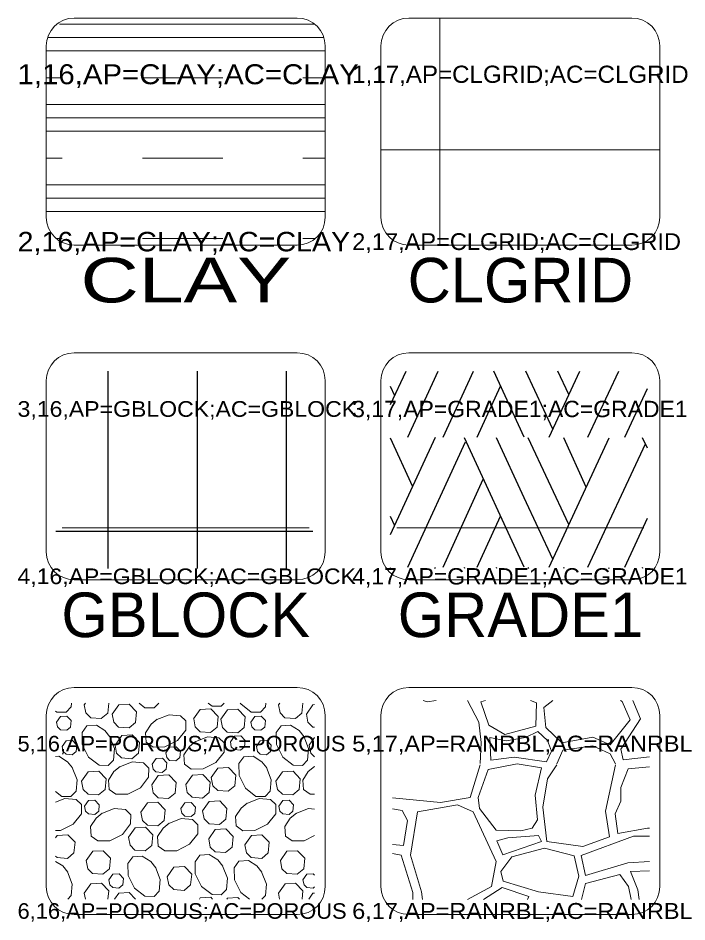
# Model space of a CAD drawing. Extents: x 95935 to 95946.4, y 95971.2 to 95974.7.
# Drawn here: x 95944.035 to 95945.234, y 95973.111 to 95974.732 of the extents above; entities that cross this region are included whole.
import ezdxf
from ezdxf.enums import TextEntityAlignment as Align

# ---------------------------------------------------------------- set-up
doc = ezdxf.new("R2010")
doc.units = 0
doc.header["$LTSCALE"] = 0.013
for name, color, linetype, lineweight in [('1', 7, 'Continuous', 13), ('25', 7, 'Continuous', 13), ('6', 7, 'Continuous', 13), ('63', 7, 'Continuous', 13)]:
    doc.layers.add(name, color=color, linetype=linetype, lineweight=lineweight)
doc.layers.add('20', color=7, linetype='Continuous')

msp = doc.modelspace()

# ---------------------------------------------------------------- linework, layer by layer
at = {"layer": '1'}
for p, q in [((95944.1357, 95974.7318), (95944.5357, 95974.7318)), ((95944.7357, 95974.7318), (95945.1357, 95974.7318)), ((95944.0857, 95974.3747), (95944.0857, 95974.6818)), ((95944.5857, 95974.6818), (95944.5857, 95974.3747)), ((95944.6857, 95974.3747), (95944.6857, 95974.6818)), ((95945.1857, 95974.6818), (95945.1857, 95974.3747)), ((95944.5357, 95974.3247), (95944.1357, 95974.3247)), ((95945.1357, 95974.3247), (95944.7357, 95974.3247)), ((95944.1357, 95974.1318), (95944.5357, 95974.1318)), ((95944.7357, 95974.1318), (95945.1357, 95974.1318)), ((95944.0857, 95973.7747), (95944.0857, 95974.0818)), ((95944.5857, 95974.0818), (95944.5857, 95973.7747)), ((95944.6857, 95973.7747), (95944.6857, 95974.0818)), ((95945.1857, 95974.0818), (95945.1857, 95973.7747)), ((95944.5357, 95973.7247), (95944.1357, 95973.7247)), ((95945.1357, 95973.7247), (95944.7357, 95973.7247)), ((95944.1357, 95973.5318), (95944.5357, 95973.5318)), ((95944.7357, 95973.5318), (95945.1357, 95973.5318)), ((95944.0857, 95973.1747), (95944.0857, 95973.4818)), ((95944.5857, 95973.4818), (95944.5857, 95973.1747)), ((95944.6857, 95973.1747), (95944.6857, 95973.4818)), ((95945.1857, 95973.4818), (95945.1857, 95973.1747)), ((95944.5357, 95973.1247), (95944.1357, 95973.1247)), ((95945.1357, 95973.1247), (95944.7357, 95973.1247))]:
    msp.add_line(p, q, dxfattribs=at)
for centre, start, end in [((95944.1357, 95974.6818), 90, 180), ((95944.5357, 95974.6818), 0, 90), ((95944.7357, 95974.6818), 90, 180), ((95945.1357, 95974.6818), 0, 90), ((95944.1357, 95974.3747), 180, 270), ((95944.5357, 95974.3747), 270, 0), ((95944.7357, 95974.3747), 180, 270), ((95945.1357, 95974.3747), 270, 0), ((95944.1357, 95974.0818), 90, 180), ((95944.5357, 95974.0818), 0, 90), ((95944.7357, 95974.0818), 90, 180), ((95945.1357, 95974.0818), 0, 90), ((95944.1357, 95973.7747), 180, 270), ((95944.5357, 95973.7747), 270, 0), ((95944.7357, 95973.7747), 180, 270), ((95945.1357, 95973.7747), 270, 0), ((95944.1357, 95973.4818), 90, 180), ((95944.5357, 95973.4818), 0, 90), ((95944.7357, 95973.4818), 90, 180), ((95945.1357, 95973.4818), 0, 90), ((95944.1357, 95973.1747), 180, 270), ((95944.5357, 95973.1747), 270, 0), ((95944.7357, 95973.1747), 180, 270), ((95945.1357, 95973.1747), 270, 0)]:
    msp.add_arc(centre, 0.05, start, end, dxfattribs=at)
at = {"layer": '25'}
for p, q in [((95944.5569, 95973.8178), (95944.1141, 95973.8178)), ((95945.1569, 95973.8178), (95944.7141, 95973.8178))]:
    msp.add_line(p, q, dxfattribs=at)
at = {"layer": '6'}
for p, q in [((95944.7912, 95974.7318), (95944.7912, 95974.3247)), ((95944.1094, 95974.7208), (95944.5657, 95974.7208)), ((95944.0887, 95974.6968), (95944.5827, 95974.6968)), ((95944.0857, 95974.6728), (95944.5857, 95974.6728)), ((95944.0857, 95974.6248), (95944.1139, 95974.6248)), ((95944.2579, 95974.6248), (95944.4019, 95974.6248)), ((95944.5459, 95974.6248), (95944.5857, 95974.6248)), ((95944.0857, 95974.5768), (95944.5857, 95974.5768)), ((95944.0857, 95974.5528), (95944.5857, 95974.5528)), ((95944.0857, 95974.5288), (95944.5857, 95974.5288)), ((95944.6857, 95974.4957), (95945.1857, 95974.4957)), ((95944.0857, 95974.4808), (95944.1139, 95974.4808)), ((95944.2579, 95974.4808), (95944.4019, 95974.4808)), ((95944.5459, 95974.4808), (95944.5857, 95974.4808)), ((95944.0857, 95974.4328), (95944.5857, 95974.4328)), ((95944.0857, 95974.4088), (95944.5857, 95974.4088)), ((95944.0857, 95974.3848), (95944.5857, 95974.3848)), ((95944.1041, 95974.3368), (95944.1139, 95974.3368)), ((95944.2579, 95974.3368), (95944.4019, 95974.3368)), ((95944.5459, 95974.3368), (95944.5673, 95974.3368)), ((95944.1537, 95973.5007), (95944.1559, 95973.5038)), ((95944.502, 95973.5007), (95944.5042, 95973.5038)), ((95944.8729, 95973.5082), (95944.8646, 95973.5063)), ((95944.5572, 95973.4286), (95944.5667, 95973.4421)), ((95945.1672, 95973.4073), (95945.12, 95973.4022)), ((95944.5655, 95973.3895), (95944.5667, 95973.39)), ((95944.7066, 95973.2505), (95944.7259, 95973.2487)), ((95945.0527, 95973.1801), (95945.0454, 95973.1517)), ((95944.1558, 95973.1523), (95944.1537, 95973.1628)), ((95944.504, 95973.1523), (95944.502, 95973.1628))]:
    msp.add_line(p, q, dxfattribs=at)
at = {"layer": '6', "lineweight": 25}
for p, q in [((95944.1959, 95974.099), (95944.1959, 95973.7451)), ((95944.3559, 95974.099), (95944.3559, 95973.7451)), ((95944.5159, 95974.099), (95944.5159, 95973.7451)), ((95944.7029, 95974.0388), (95944.7307, 95974.099)), ((95944.7336, 95973.9803), (95944.7884, 95974.099)), ((95944.7971, 95973.9803), (95944.8513, 95974.099)), ((95944.9427, 95973.9803), (95944.8878, 95974.099)), ((95944.9939, 95973.9948), (95944.9452, 95974.099)), ((95944.9874, 95973.9803), (95945.0423, 95974.099)), ((95945.0227, 95974.0568), (95945.003, 95974.099)), ((95945.0566, 95973.9803), (95945.1119, 95974.099)), ((95944.7105, 95974.0546), (95944.7029, 95974.0711)), ((95944.8583, 95973.9803), (95944.9002, 95974.0719)), ((95945.1229, 95973.9803), (95945.1636, 95974.0679)), ((95944.7029, 95973.806), (95944.7834, 95973.9803)), ((95944.743, 95973.8917), (95944.7029, 95973.9789)), ((95944.7336, 95973.7475), (95944.8374, 95973.9724)), ((95944.9427, 95973.7475), (95944.8353, 95973.9796)), ((95944.9427, 95973.8715), (95944.893, 95973.9796)), ((95945.0227, 95973.8239), (95944.9499, 95973.9796)), ((95944.9874, 95973.7475), (95945.0948, 95973.9796)), ((95945.0537, 95973.8909), (95945.0134, 95973.9796)), ((95945.0566, 95973.7475), (95945.1597, 95973.9688)), ((95945.1636, 95973.9605), (95945.1547, 95973.9796)), ((95944.7971, 95973.7475), (95944.8692, 95973.9054)), ((95944.9939, 95973.7619), (95944.9427, 95973.8715)), ((95944.7105, 95973.8217), (95944.7029, 95973.8382)), ((95944.8583, 95973.7475), (95944.9002, 95973.839)), ((95945.1229, 95973.7475), (95945.1636, 95973.8351)), ((95944.1029, 95973.8118), (95944.5636, 95973.8118)), ((95944.7033, 95973.7451), (95944.7029, 95973.746)), ((95944.7823, 95973.7451), (95944.7834, 95973.7475)), ((95944.836, 95973.7451), (95944.8353, 95973.7467)), ((95944.8937, 95973.7451), (95944.893, 95973.7467)), ((95944.9506, 95973.7451), (95944.9499, 95973.7467)), ((95945.0141, 95973.7451), (95945.0134, 95973.7467)), ((95945.0941, 95973.7451), (95945.0948, 95973.7467)), ((95945.1554, 95973.7451), (95945.1547, 95973.7467))]:
    msp.add_line(p, q, dxfattribs=at)
at = {"layer": '6'}
for points in [[(95944.131, 95973.5038), (95944.1304, 95973.497), (95944.1212, 95973.4873), (95944.1047, 95973.4876), (95944.1021, 95973.4896)], [(95944.1975, 95973.5038), (95944.1957, 95973.4859), (95944.184, 95973.4762), (95944.1653, 95973.4776), (95944.1566, 95973.4861), (95944.1537, 95973.5007)], [(95944.2873, 95973.5038), (95944.2791, 95973.4952), (95944.2626, 95973.4955), (95944.2519, 95973.5038)], [(95944.4048, 95973.5038), (95944.3993, 95973.498), (95944.3828, 95973.4983), (95944.3758, 95973.5038)], [(95944.4793, 95973.5038), (95944.4787, 95973.497), (95944.4695, 95973.4873), (95944.453, 95973.4876), (95944.4342, 95973.5023), (95944.4335, 95973.5038)], [(95944.5457, 95973.5038), (95944.5439, 95973.4859), (95944.5323, 95973.4762), (95944.5136, 95973.4776), (95944.5048, 95973.4861), (95944.502, 95973.5007)], [(95944.552, 95973.484), (95944.5638, 95973.5008), (95944.5667, 95973.501)], [(95944.7613, 95973.5082), (95944.7683, 95973.5063), (95944.7848, 95973.5082)], [(95944.8411, 95973.5082), (95944.8611, 95973.4698), (95944.8655, 95973.4334), (95944.8634, 95973.3953)], [(95944.8646, 95973.5063), (95944.8789, 95973.4645), (95944.9075, 95973.4476), (95944.9636, 95973.4627), (95944.9645, 95973.5045), (95944.9537, 95973.5082)], [(95944.9937, 95973.5082), (95944.9777, 95973.496), (95944.9812, 95973.4603), (95945.0099, 95973.4326)], [(95945.0099, 95973.4326), (95945.0654, 95973.4424), (95945.0967, 95973.429), (95945.1325, 95973.4737), (95945.1182, 95973.5067), (95945.1149, 95973.5082)], [(95945.12, 95973.4022), (95945.1155, 95973.421), (95945.1513, 95973.4755), (95945.1372, 95973.5082)], [(95944.2838, 95973.4741), (95944.306, 95973.4829), (95944.3263, 95973.4812), (95944.336, 95973.472), (95944.3357, 95973.4555), (95944.321, 95973.4367), (95944.2983, 95973.4254), (95944.277, 95973.425), (95944.2649, 95973.4336), (95944.2638, 95973.4506), (95944.2736, 95973.4658), (95944.2847, 95973.4747)], [(95944.3498, 95973.4757), (95944.3617, 95973.4925), (95944.3806, 95973.4936), (95944.3937, 95973.48), (95944.3918, 95973.4609), (95944.3801, 95973.4512), (95944.3615, 95973.4525), (95944.3527, 95973.461), (95944.3499, 95973.4757)], [(95944.5667, 95973.4607), (95944.5636, 95973.4609), (95944.5548, 95973.4694), (95944.552, 95973.484)], [(95944.1989, 95973.4442), (95944.2077, 95973.4221), (95944.2059, 95973.4017), (95944.1968, 95973.3921), (95944.1803, 95973.3924), (95944.1615, 95973.4071), (95944.1502, 95973.4297), (95944.1498, 95973.4511), (95944.1583, 95973.4631), (95944.1754, 95973.4643), (95944.1906, 95973.4545), (95944.1995, 95973.4433)], [(95944.5472, 95973.4442), (95944.5559, 95973.4221), (95944.5542, 95973.4017), (95944.545, 95973.3921), (95944.5285, 95973.3924), (95944.5098, 95973.4071), (95944.4984, 95973.4297), (95944.498, 95973.4511), (95944.5066, 95973.4631), (95944.5236, 95973.4643), (95944.5388, 95973.4545), (95944.5477, 95973.4433)], [(95944.3525, 95973.4346), (95944.3747, 95973.4434), (95944.395, 95973.4416), (95944.4046, 95973.4324), (95944.4043, 95973.4159), (95944.3897, 95973.3972), (95944.367, 95973.3858), (95944.3456, 95973.3855), (95944.3336, 95973.394), (95944.3325, 95973.411), (95944.3422, 95973.4262), (95944.3534, 95973.4352)], [(95944.4157, 95973.4343), (95944.4228, 95973.4444), (95944.4342, 95973.445), (95944.442, 95973.4368), (95944.4409, 95973.4254), (95944.4339, 95973.4196), (95944.4227, 95973.4204), (95944.4174, 95973.4255), (95944.4157, 95973.4342)], [(95944.5667, 95973.4076), (95944.5601, 95973.414), (95944.5572, 95973.4286)], [(95945.0013, 95973.3951), (95945.0117, 95973.4192), (95945.0654, 95973.4272), (95945.0967, 95973.4129), (95945.1063, 95973.3951)], [(95944.1021, 95973.408), (95944.1084, 95973.4084), (95944.1236, 95973.3987), (95944.1325, 95973.3875)], [(95944.4802, 95973.3884), (95944.489, 95973.3663), (95944.4872, 95973.3459), (95944.4781, 95973.3362), (95944.4616, 95973.3366), (95944.4428, 95973.3512), (95944.4315, 95973.3739), (95944.4311, 95973.3953), (95944.4396, 95973.4073), (95944.4567, 95973.4084), (95944.4719, 95973.3987), (95944.4808, 95973.3875)], [(95944.132, 95973.3884), (95944.1407, 95973.3663), (95944.139, 95973.3459), (95944.1298, 95973.3362), (95944.1133, 95973.3366), (95944.1021, 95973.3453)], [(95944.2172, 95973.3895), (95944.2394, 95973.3983), (95944.2597, 95973.3965), (95944.2694, 95973.3873), (95944.2691, 95973.3708), (95944.2544, 95973.3521), (95944.2317, 95973.3408), (95944.2104, 95973.3404), (95944.1984, 95973.3489), (95944.1972, 95973.3659), (95944.207, 95973.3812), (95944.2181, 95973.3901)], [(95944.5667, 95973.3406), (95944.5586, 95973.3404), (95944.5466, 95973.3489), (95944.5455, 95973.3659), (95944.5552, 95973.3812), (95944.5664, 95973.3901)], [(95944.7066, 95973.3341), (95944.7925, 95973.3255), (95944.8456, 95973.3348), (95944.8634, 95973.3931)], [(95945.0008, 95973.3933), (95944.984, 95973.3681), (95944.9757, 95973.3172), (95944.983, 95973.2559), (95945.0475, 95973.2466), (95945.0954, 95973.2642), (95945.0881, 95973.3099), (95945.1063, 95973.3928)], [(95945.1672, 95973.3896), (95945.1291, 95973.3858), (95945.1159, 95973.3526), (95945.1159, 95973.328), (95945.1054, 95973.3053), (95945.1102, 95973.2702)], [(95944.1021, 95973.3261), (95944.119, 95973.3328), (95944.1393, 95973.3311), (95944.149, 95973.3219), (95944.1487, 95973.3054), (95944.134, 95973.2866), (95944.1114, 95973.2753), (95944.1021, 95973.2751)], [(95944.327, 95973.315), (95944.3341, 95973.3251), (95944.3454, 95973.3257), (95944.3533, 95973.3175), (95944.3521, 95973.3061), (95944.3451, 95973.3003), (95944.3339, 95973.3011), (95944.3287, 95973.3062), (95944.327, 95973.3149)], [(95944.4451, 95973.324), (95944.4673, 95973.3328), (95944.4876, 95973.3311), (95944.4973, 95973.3219), (95944.497, 95973.3054), (95944.4823, 95973.2866), (95944.4596, 95973.2753), (95944.4383, 95973.2749), (95944.4262, 95973.2835), (95944.4251, 95973.3005), (95944.4349, 95973.3157), (95944.446, 95973.3246)], [(95944.8411, 95973.1517), (95944.8841, 95973.1749), (95944.8925, 95973.2196), (95944.8508, 95973.3089), (95944.8227, 95973.3213), (95944.7509, 95973.3089)], [(95944.1851, 95973.3059), (95944.2072, 95973.3146), (95944.2275, 95973.3129), (95944.2372, 95973.3037), (95944.2369, 95973.2872), (95944.2222, 95973.2685), (95944.1996, 95973.2571), (95944.1782, 95973.2567), (95944.1662, 95973.2653), (95944.165, 95973.2823), (95944.1748, 95973.2975), (95944.186, 95973.3064)], [(95944.5667, 95973.2666), (95944.5478, 95973.2571), (95944.5264, 95973.2567), (95944.5144, 95973.2653), (95944.5133, 95973.2823), (95944.523, 95973.2975), (95944.5342, 95973.3064)], [(95944.5333, 95973.3059), (95944.5555, 95973.3146), (95944.5667, 95973.3137)], [(95944.7259, 95973.2487), (95944.7332, 95973.2933), (95944.7238, 95973.311), (95944.7066, 95973.3143)], [(95944.7509, 95973.3089), (95944.7384, 95973.231), (95944.7582, 95973.1656), (95944.7601, 95973.1517)], [(95944.3053, 95973.288), (95944.3275, 95973.2968), (95944.3478, 95973.295), (95944.3574, 95973.2858), (95944.3571, 95973.2693), (95944.3425, 95973.2506), (95944.3198, 95973.2392), (95944.2984, 95973.2389), (95944.2864, 95973.2474), (95944.2853, 95973.2644), (95944.295, 95973.2796), (95944.3062, 95973.2885)], [(95945.1102, 95973.2702), (95945.1633, 95973.2797), (95945.1672, 95973.2798)], [(95944.1021, 95973.2624), (95944.1051, 95973.2667), (95944.124, 95973.2678), (95944.1372, 95973.2542), (95944.1353, 95973.2351), (95944.1236, 95973.2254), (95944.1049, 95973.2268), (95944.1021, 95973.2295)], [(95945.1672, 95973.2655), (95945.1386, 95973.2655), (95945.0447, 95973.2305), (95945.0523, 95973.1945)], [(95944.2812, 95973.2094), (95944.29, 95973.1873), (95944.2883, 95973.1669), (95944.2791, 95973.1573), (95944.2626, 95973.1576), (95944.2438, 95973.1722), (95944.2325, 95973.1949), (95944.2321, 95973.2163), (95944.2407, 95973.2283), (95944.2577, 95973.2294), (95944.2729, 95973.2197), (95944.2818, 95973.2085)], [(95944.4015, 95973.2123), (95944.4103, 95973.1901), (95944.4085, 95973.1698), (95944.3993, 95973.1601), (95944.3828, 95973.1604), (95944.3641, 95973.1751), (95944.3527, 95973.1978), (95944.3524, 95973.2191), (95944.3609, 95973.2312), (95944.3779, 95973.2323), (95944.3931, 95973.2225), (95944.4021, 95973.2114)], [(95944.7426, 95973.1517), (95944.7426, 95973.1645), (95944.7218, 95973.231), (95944.7066, 95973.2342)], [(95944.1021, 95973.2201), (95944.115, 95973.2118), (95944.124, 95973.2006)], [(95944.4497, 95973.1523), (95944.4342, 95973.1644), (95944.4229, 95973.187), (95944.4225, 95973.2084), (95944.4311, 95973.2204), (95944.4481, 95973.2216), (95944.4633, 95973.2118), (95944.4722, 95973.2006)], [(95945.0523, 95973.1945), (95945.1282, 95973.2172), (95945.1672, 95973.2197)], [(95944.1234, 95973.2015), (95944.1322, 95973.1794), (95944.1304, 95973.159), (95944.124, 95973.1523)], [(95944.4716, 95973.2015), (95944.4804, 95973.1794), (95944.4787, 95973.159), (95944.4723, 95973.1523)], [(95944.5459, 95973.1868), (95944.553, 95973.1969), (95944.5644, 95973.1975), (95944.5667, 95973.1951)], [(95945.1342, 95973.1517), (95945.1298, 95973.1749), (95945.1141, 95973.1967), (95945.0527, 95973.1801)], [(95945.1672, 95973.2031), (95945.1329, 95973.202), (95945.1462, 95973.1689), (95945.1484, 95973.1517)], [(95944.1537, 95973.1628), (95944.1655, 95973.1797), (95944.1844, 95973.1807), (95944.1976, 95973.1671), (95944.1961, 95973.1523)], [(95944.502, 95973.1628), (95944.5138, 95973.1797), (95944.5327, 95973.1807), (95944.5458, 95973.1671), (95944.5443, 95973.1523)], [(95944.5667, 95973.1743), (95944.5641, 95973.1721), (95944.5529, 95973.1729), (95944.5477, 95973.178), (95944.5459, 95973.1868)], [(95944.2081, 95973.1523), (95944.2155, 95973.1629), (95944.2344, 95973.164), (95944.2458, 95973.1523)], [(95944.5564, 95973.1523), (95944.5638, 95973.1629), (95944.5667, 95973.1631)], [(95944.8697, 95973.1517), (95944.9029, 95973.1729), (95944.9507, 95973.1573), (95944.9485, 95973.1517)], [(95944.3601, 95973.1523), (95944.3617, 95973.1546), (95944.3806, 95973.1557), (95944.3839, 95973.1523)], [(95944.4092, 95973.1523), (95944.4103, 95973.1539), (95944.4292, 95973.155), (95944.4318, 95973.1523)]]:
    msp.add_lwpolyline(points, dxfattribs=at)
for points in [[(95944.2037, 95973.484), (95944.2155, 95973.5008), (95944.2344, 95973.5019), (95944.2476, 95973.4883), (95944.2457, 95973.4692), (95944.234, 95973.4595), (95944.2153, 95973.4609), (95944.2066, 95973.4694)], [(95944.3985, 95973.475), (95944.4103, 95973.4918), (95944.4292, 95973.4929), (95944.4424, 95973.4793), (95944.4405, 95973.4602), (95944.4288, 95973.4505), (95944.4101, 95973.4518), (95944.4014, 95973.4603)], [(95944.1041, 95973.4698), (95944.1112, 95973.4799), (95944.1225, 95973.4805), (95944.1304, 95973.4723), (95944.1293, 95973.4609), (95944.1223, 95973.4551), (95944.1111, 95973.4559), (95944.1058, 95973.461)], [(95944.4524, 95973.4698), (95944.4595, 95973.4799), (95944.4708, 95973.4805), (95944.4787, 95973.4723), (95944.4775, 95973.4609), (95944.4705, 95973.4551), (95944.4593, 95973.4559), (95944.4541, 95973.461)], [(95944.8825, 95973.4013), (95944.9244, 95973.4067), (95944.9824, 95973.3987), (95944.9913, 95973.4174), (95944.9841, 95973.4369), (95944.9672, 95973.4529), (95944.9449, 95973.4423), (95944.9101, 95973.436), (95944.8807, 95973.4423)], [(95944.1141, 95973.4259), (95944.1212, 95973.436), (95944.1325, 95973.4367), (95944.1404, 95973.4285), (95944.1393, 95973.4171), (95944.1323, 95973.4112), (95944.1211, 95973.412), (95944.1158, 95973.4171)], [(95944.209, 95973.4286), (95944.2208, 95973.4455), (95944.2397, 95973.4466), (95944.2528, 95973.4329), (95944.2509, 95973.4139), (95944.2393, 95973.4041), (95944.2206, 95973.4055), (95944.2118, 95973.414)], [(95944.4623, 95973.4259), (95944.4694, 95973.436), (95944.4808, 95973.4367), (95944.4887, 95973.4285), (95944.4875, 95973.4171), (95944.4805, 95973.4112), (95944.4693, 95973.412), (95944.4641, 95973.4171)], [(95944.2998, 95973.4148), (95944.3069, 95973.4249), (95944.3182, 95973.4256), (95944.3261, 95973.4174), (95944.3249, 95973.406), (95944.3179, 95973.4001), (95944.3068, 95973.4009), (95944.3015, 95973.4061)], [(95944.2754, 95973.3943), (95944.2825, 95973.4044), (95944.2938, 95973.405), (95944.3017, 95973.3969), (95944.3005, 95973.3854), (95944.2935, 95973.3796), (95944.2823, 95973.3804), (95944.2771, 95973.3855)], [(95944.3815, 95973.3704), (95944.3933, 95973.3872), (95944.4122, 95973.3883), (95944.4254, 95973.3746), (95944.4235, 95973.3556), (95944.4118, 95973.3459), (95944.3931, 95973.3472), (95944.3844, 95973.3557)], [(95944.8779, 95973.3847), (95944.9299, 95973.3951), (95944.9736, 95973.3878), (95944.9622, 95973.339), (95944.9663, 95973.2943), (95944.957, 95973.2798), (95944.9362, 95973.2746), (95944.8925, 95973.2757), (95944.8623, 95973.3151), (95944.8602, 95973.3348)], [(95944.149, 95973.3636), (95944.1608, 95973.3804), (95944.1797, 95973.3815), (95944.1929, 95973.3678), (95944.191, 95973.3488), (95944.1793, 95973.3391), (95944.1606, 95973.3404), (95944.1519, 95973.3489)], [(95944.2746, 95973.3573), (95944.2864, 95973.3741), (95944.3053, 95973.3752), (95944.3184, 95973.3616), (95944.3165, 95973.3425), (95944.3049, 95973.3328), (95944.2862, 95973.3342), (95944.2774, 95973.3427)], [(95944.3356, 95973.358), (95944.3475, 95973.3748), (95944.3663, 95973.3759), (95944.3795, 95973.3623), (95944.3776, 95973.3432), (95944.3659, 95973.3335), (95944.3473, 95973.3349), (95944.3385, 95973.3434)], [(95944.4973, 95973.3636), (95944.5091, 95973.3804), (95944.528, 95973.3815), (95944.5411, 95973.3678), (95944.5392, 95973.3488), (95944.5276, 95973.3391), (95944.5089, 95973.3404), (95944.5001, 95973.3489)], [(95944.1544, 95973.3188), (95944.1615, 95973.3289), (95944.1728, 95973.3296), (95944.1807, 95973.3214), (95944.1796, 95973.31), (95944.1726, 95973.3041), (95944.1614, 95973.305), (95944.1561, 95973.3101)], [(95944.2552, 95973.308), (95944.267, 95973.3249), (95944.2859, 95973.3259), (95944.299, 95973.3123), (95944.2971, 95973.2932), (95944.2855, 95973.2835), (95944.2668, 95973.2849), (95944.258, 95973.2934)], [(95944.3657, 95973.3106), (95944.3776, 95973.3274), (95944.3965, 95973.3285), (95944.4096, 95973.3149), (95944.4077, 95973.2958), (95944.396, 95973.2861), (95944.3774, 95973.2874), (95944.3686, 95973.296)], [(95944.5027, 95973.3188), (95944.5098, 95973.3289), (95944.5211, 95973.3296), (95944.529, 95973.3214), (95944.5278, 95973.31), (95944.5208, 95973.3041), (95944.5096, 95973.305), (95944.5044, 95973.3101)], [(95944.2329, 95973.2635), (95944.2447, 95973.2803), (95944.2636, 95973.2814), (95944.2768, 95973.2678), (95944.2749, 95973.2487), (95944.2632, 95973.239), (95944.2445, 95973.2404), (95944.2358, 95973.2489)], [(95944.3769, 95973.2602), (95944.3887, 95973.277), (95944.4076, 95973.2781), (95944.4207, 95973.2645), (95944.4188, 95973.2454), (95944.4072, 95973.2357), (95944.3885, 95973.2371), (95944.3797, 95973.2456)], [(95944.4416, 95973.2499), (95944.4534, 95973.2667), (95944.4723, 95973.2678), (95944.4854, 95973.2542), (95944.4835, 95973.2351), (95944.4718, 95973.2254), (95944.4532, 95973.2268), (95944.4444, 95973.2353)], [(95944.9039, 95973.232), (95944.9736, 95973.2559), (95944.9684, 95973.2663), (95944.9133, 95973.2622), (95944.8935, 95973.257)], [(95944.9049, 95973.1843), (95944.9684, 95973.1656), (95945.0298, 95973.1573), (95945.0402, 95973.1936), (95945.0319, 95973.23), (95944.9788, 95973.2435), (95944.9206, 95973.2279), (95944.9008, 95973.2019)], [(95944.157, 95973.2213), (95944.1689, 95973.2381), (95944.1878, 95973.2392), (95944.2009, 95973.2256), (95944.199, 95973.2065), (95944.1873, 95973.1968), (95944.1687, 95973.1981), (95944.1599, 95973.2066)], [(95944.5053, 95973.2213), (95944.5171, 95973.2381), (95944.536, 95973.2392), (95944.5491, 95973.2256), (95944.5472, 95973.2065), (95944.5356, 95973.1968), (95944.5169, 95973.1981), (95944.5081, 95973.2066)], [(95944.3025, 95973.1926), (95944.3143, 95973.2095), (95944.3332, 95973.2106), (95944.3463, 95973.1969), (95944.3444, 95973.1779), (95944.3328, 95973.1681), (95944.3141, 95973.1695), (95944.3053, 95973.178)], [(95944.1977, 95973.1868), (95944.2048, 95973.1969), (95944.2161, 95973.1975), (95944.224, 95973.1894), (95944.2229, 95973.1779), (95944.2159, 95973.1721), (95944.2047, 95973.1729), (95944.1994, 95973.178)]]:
    msp.add_lwpolyline(points, close=True, dxfattribs=at)

# ---------------------------------------------------------------- texts
at = {"layer": '20', "width": 1.35}
msp.add_text(' CLAY ', height=0.08, dxfattribs=at).set_placement((95944.3357, 95974.222), align=Align.CENTER)
at = {"layer": '20'}
for s, p in [('CLGRID', (95944.9357, 95974.222)), ('GBLOCK', (95944.3357, 95973.622)), ('GRADE1', (95944.9358, 95973.622))]:
    msp.add_text(s, height=0.08, dxfattribs=at).set_placement(p, align=Align.CENTER)
at = {"layer": '63'}
for s, height, width, p in [('1,16,AP=CLAY;AC=CLAY', 0.0358, 1.1, (95944.0341, 95974.6132)), ('1,17,AP=CLGRID;AC=CLGRID', 0.0308, 1.05, (95944.6341, 95974.6157)), ('2,16,AP=CLAY;AC=CLAY', 0.0349, 1.1, (95944.0341, 95974.3136)), ('2,17,AP=CLGRID;AC=CLGRID', 0.0301, 1.05, (95944.6341, 95974.316)), ('3,16,AP=GBLOCK;AC=GBLOCK', 0.0281, 1.1, (95944.0341, 95974.017)), ('3,17,AP=GRADE1;AC=GRADE1', 0.0293, 1.05, (95944.6341, 95974.0164)), ('4,16,AP=GBLOCK;AC=GBLOCK', 0.028, 1.1, (95944.0341, 95973.7171)), ('4,17,AP=GRADE1;AC=GRADE1', 0.0293, 1.05, (95944.6341, 95973.7164)), ('5,16,AP=POROUS;AC=POROUS', 0.0278, 1.05, (95944.0341, 95973.4172)), ('5,17,AP=RANRBL;AC=RANRBL', 0.0286, 1.1, (95944.6341, 95973.4168)), ('6,16,AP=POROUS;AC=POROUS', 0.0279, 1.05, (95944.0341, 95973.1171)), ('6,17,AP=RANRBL;AC=RANRBL', 0.0286, 1.1, (95944.6341, 95973.1168))]:
    msp.add_text(s, height=height, dxfattribs=dict(at, width=width)).set_placement(p)

doc.saveas('drawing.dxf')
